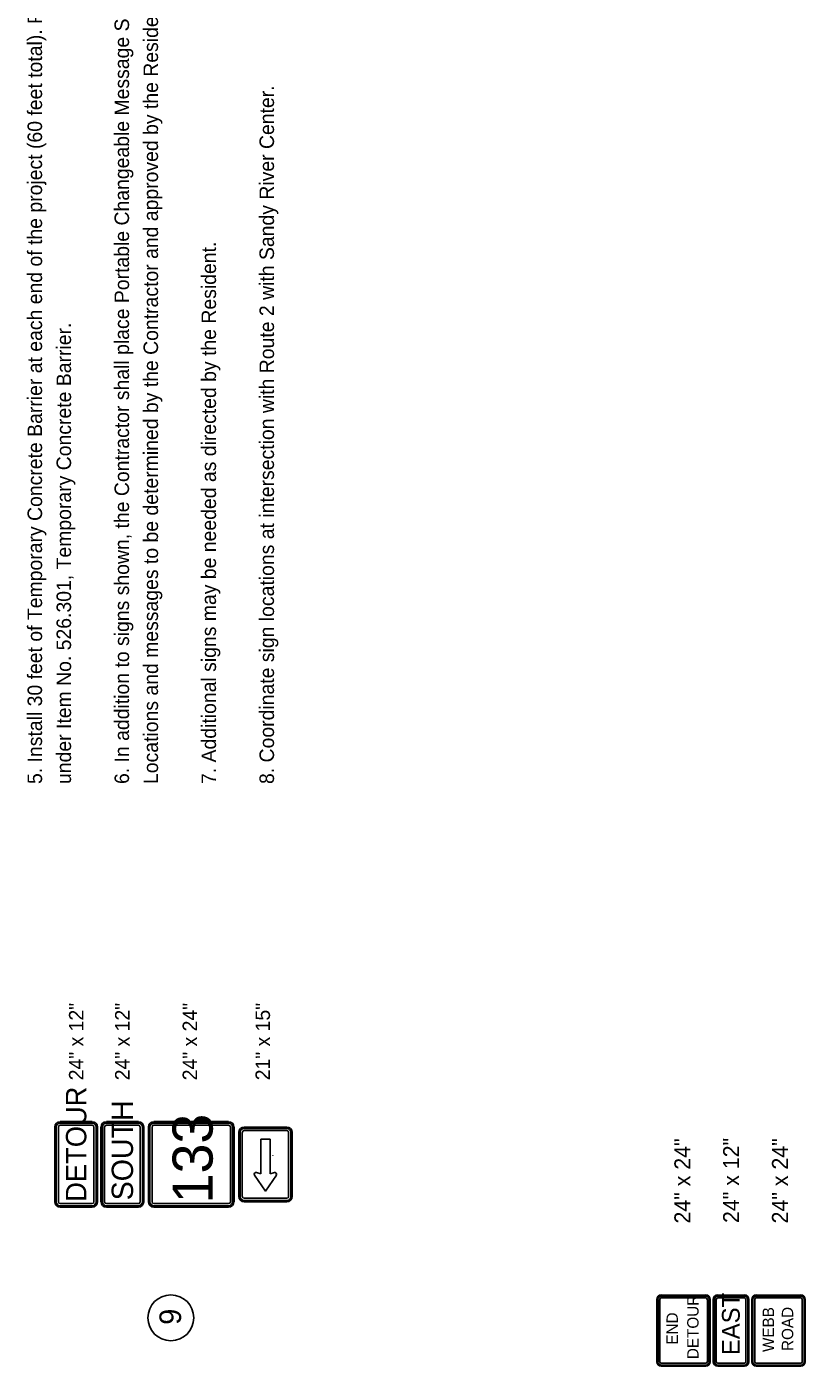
# Model space of a CAD drawing. Extents: x 1123038 to 1172987, y 554419 to 623636.
# Drawn here: x 1166973 to 1172987, y 559217 to 569560 of the extents above; entities that cross this region are included whole.
import ezdxf

# ---------------------------------------------------------------- set-up
doc = ezdxf.new("R2010")
doc.units = 0
for name, color, linetype in [('D_Text_Standard', 7, 'Continuous'), ('Default', 7, 'Continuous'), ('SIGNS TRAFFIC', 7, 'Continuous')]:
    doc.layers.add(name, color=color, linetype=linetype)

msp = doc.modelspace()

# ---------------------------------------------------------------- linework, layer by layer
at = {"layer": 'D_Text_Standard'}
msp.add_circle((1168086, 559591), 177, dxfattribs=at)
at = {"layer": 'Default'}
for p, q in [((1172219, 559767), (1171875, 559767)), ((1172517, 559767), (1172311, 559767)), ((1172952, 559767), (1172609, 559767)), ((1171841, 559733), (1171841, 559252)), ((1171850, 559733), (1171850, 559252)), ((1171864, 559252), (1171864, 559733)), ((1172219, 559759), (1171875, 559759)), ((1171875, 559744), (1172219, 559744)), ((1172231, 559733), (1172231, 559252)), ((1172245, 559252), (1172245, 559733)), ((1172253, 559252), (1172253, 559733)), ((1172276, 559733), (1172276, 559252)), ((1172285, 559733), (1172285, 559252)), ((1172299, 559252), (1172299, 559733)), ((1172517, 559759), (1172311, 559759)), ((1172311, 559744), (1172517, 559744)), ((1172528, 559733), (1172528, 559252)), ((1172543, 559252), (1172543, 559733)), ((1172551, 559252), (1172551, 559733)), ((1172574, 559733), (1172574, 559252)), ((1172583, 559733), (1172583, 559252)), ((1172597, 559252), (1172597, 559733)), ((1172952, 559759), (1172609, 559759)), ((1172609, 559744), (1172952, 559744)), ((1172964, 559733), (1172964, 559252)), ((1172978, 559252), (1172978, 559733)), ((1172987, 559252), (1172987, 559733)), ((1172219, 559240), (1171875, 559240)), ((1171875, 559226), (1172219, 559226)), ((1171875, 559217), (1172219, 559217)), ((1172517, 559240), (1172311, 559240)), ((1172311, 559226), (1172517, 559226)), ((1172311, 559217), (1172517, 559217)), ((1172952, 559240), (1172609, 559240)), ((1172609, 559226), (1172952, 559226)), ((1172609, 559217), (1172952, 559217))]:
    msp.add_line(p, q, dxfattribs=at)
for centre, radius, start, end in [((1171875, 559733), 34.4, 90, 180), ((1172219, 559733), 34.4, 0, 90), ((1172311, 559733), 34.4, 90, 180), ((1172517, 559733), 34.4, 0, 90), ((1172609, 559733), 34.4, 90, 180), ((1172952, 559733), 34.4, 0, 90), ((1171875, 559733), 25.8, 90, 180), ((1171875, 559733), 11.5, 90, 180), ((1172219, 559733), 25.8, 0, 90), ((1172219, 559733), 11.5, 0, 90), ((1172311, 559733), 25.8, 90, 180), ((1172311, 559733), 11.5, 90, 180), ((1172517, 559733), 25.8, 0, 90), ((1172517, 559733), 11.5, 0, 90), ((1172609, 559733), 25.8, 90, 180), ((1172609, 559733), 11.5, 90, 180), ((1172952, 559733), 25.8, 0, 90), ((1172952, 559733), 11.5, 0, 90), ((1171875, 559252), 34.4, 180, 270), ((1171875, 559252), 25.8, 180, 270), ((1171875, 559252), 11.5, 180, 270), ((1172219, 559252), 34.4, 270, 0), ((1172219, 559252), 25.8, 270, 0), ((1172219, 559252), 11.5, 270, 0), ((1172311, 559252), 34.4, 180, 270), ((1172311, 559252), 25.8, 180, 270), ((1172311, 559252), 11.5, 180, 270), ((1172517, 559252), 34.4, 270, 0), ((1172517, 559252), 25.8, 270, 0), ((1172517, 559252), 11.5, 270, 0), ((1172609, 559252), 34.4, 180, 270), ((1172609, 559252), 25.8, 180, 270), ((1172609, 559252), 11.5, 180, 270), ((1172952, 559252), 34.4, 270, 0), ((1172952, 559252), 25.8, 270, 0), ((1172952, 559252), 11.5, 270, 0)]:
    msp.add_arc(centre, radius, start, end, dxfattribs=at)
at = {"layer": 'SIGNS TRAFFIC'}
for p, q in [((1168621, 560528), (1168621, 561023)), ((1168781, 560702), (1168781, 560971)), ((1168781, 560971), (1168853, 560971)), ((1168853, 560971), (1168853, 560702)), ((1168747, 560713), (1168781, 560702)), ((1168853, 560702), (1168887, 560713))]:
    msp.add_line(p, q, dxfattribs=at)
for points in [[(1167231, 561106), (1167478, 561106)], [(1167231, 561106), (1167478, 561106)], [(1167588, 561106), (1167835, 561106)], [(1167588, 561106), (1167835, 561106)], [(1167955, 561106), (1168532, 561106)], [(1167955, 561106), (1168532, 561106)], [(1167190, 560487), (1167190, 561064)], [(1167190, 560487), (1167190, 561064)], [(1167200, 560487), (1167200, 561064)], [(1167217, 561064), (1167217, 560487)], [(1167231, 561095), (1167478, 561095)], [(1167478, 561078), (1167231, 561078)], [(1167492, 560487), (1167492, 561064)], [(1167509, 561064), (1167509, 560487)], [(1167520, 561064), (1167520, 560487)], [(1167520, 561064), (1167520, 560487)], [(1167546, 560487), (1167546, 561064)], [(1167546, 560487), (1167546, 561064)], [(1167557, 560487), (1167557, 561064)], [(1167574, 561064), (1167574, 560487)], [(1167588, 561095), (1167835, 561095)], [(1167835, 561078), (1167588, 561078)], [(1167849, 560487), (1167849, 561064)], [(1167866, 561064), (1167866, 560487)], [(1167876, 561064), (1167876, 560487)], [(1167876, 561064), (1167876, 560487)], [(1167914, 560487), (1167914, 561064)], [(1167914, 560487), (1167914, 561064)], [(1167924, 560487), (1167924, 561064)], [(1167941, 561064), (1167941, 560487)], [(1167955, 561095), (1168532, 561095)], [(1168532, 561078), (1167955, 561078)], [(1168546, 560487), (1168546, 561064)], [(1168563, 561064), (1168563, 560487)], [(1168574, 561064), (1168574, 560487)], [(1168574, 561064), (1168574, 560487)], [(1168610, 561023), (1168610, 560528)], [(1168638, 561023), (1168638, 560528)], [(1168982, 561064), (1168652, 561064)], [(1168652, 561054), (1168982, 561054)], [(1168982, 561037), (1168652, 561037)], [(1168995, 560528), (1168995, 561023)], [(1169013, 561023), (1169013, 560528)], [(1169023, 560528), (1169023, 561023)], [(1168875, 560846), (1168874, 560845)], [(1168901, 560693), (1168817, 560569), (1168732, 560693)], [(1168652, 560514), (1168982, 560514)], [(1168982, 560497), (1168652, 560497)], [(1168652, 560487), (1168982, 560487)], [(1167231, 560473), (1167478, 560473)], [(1167478, 560456), (1167231, 560456)], [(1167478, 560446), (1167231, 560446)], [(1167478, 560446), (1167231, 560446)], [(1167588, 560473), (1167835, 560473)], [(1167835, 560456), (1167588, 560456)], [(1167835, 560446), (1167588, 560446)], [(1167835, 560446), (1167588, 560446)], [(1167955, 560473), (1168532, 560473)], [(1168532, 560456), (1167955, 560456)], [(1168532, 560446), (1167955, 560446)], [(1168532, 560446), (1167955, 560446)]]:
    msp.add_lwpolyline(points, dxfattribs=at)
for centre, radius, start, end in [((1167231, 561064), 41.2, 90, 180), ((1167231, 561064), 41.2, 90, 180), ((1167478, 561064), 41.2, 360, 90), ((1167478, 561064), 41.2, 360, 90), ((1167588, 561064), 41.2, 90, 180), ((1167588, 561064), 41.2, 90, 180), ((1167835, 561064), 41.2, 360, 90), ((1167835, 561064), 41.2, 360, 90), ((1167955, 561064), 41.2, 90, 180), ((1167955, 561064), 41.2, 90, 180), ((1168532, 561064), 41.2, 360, 90), ((1168532, 561064), 41.2, 360, 90), ((1167231, 561064), 30.9, 90, 180), ((1167231, 561064), 13.7, 90, 180), ((1167478, 561064), 30.9, 360, 90), ((1167478, 561064), 13.7, 360, 90), ((1167588, 561064), 30.9, 90, 180), ((1167588, 561064), 13.7, 90, 180), ((1167835, 561064), 30.9, 360, 90), ((1167835, 561064), 13.7, 360, 90), ((1167955, 561064), 30.9, 90, 180), ((1167955, 561064), 13.7, 90, 180), ((1168532, 561064), 30.9, 360, 90), ((1168532, 561064), 13.7, 360, 90), ((1168652, 561023), 41.2, 90, 180), ((1168652, 561023), 30.9, 90, 180), ((1168652, 561023), 13.7, 90, 180), ((1168982, 561023), 41.2, 360, 90), ((1168982, 561023), 30.9, 360, 90), ((1168982, 561023), 13.7, 360, 90), ((1168743, 560700), 12.9, 72.1872, 214.3237), ((1168890, 560700), 12.9, 325.6763, 107.8128), ((1167231, 560487), 41.2, 180, 270), ((1167231, 560487), 41.2, 180, 270), ((1167231, 560487), 30.9, 180, 270), ((1167231, 560487), 13.7, 180, 270), ((1167478, 560487), 41.2, 270, 360), ((1167478, 560487), 41.2, 270, 360), ((1167478, 560487), 30.9, 270, 360), ((1167478, 560487), 13.7, 270, 360), ((1167588, 560487), 41.2, 180, 270), ((1167588, 560487), 41.2, 180, 270), ((1167588, 560487), 30.9, 180, 270), ((1167588, 560487), 13.7, 180, 270), ((1167835, 560487), 41.2, 270, 360), ((1167835, 560487), 41.2, 270, 360), ((1167835, 560487), 30.9, 270, 360), ((1167835, 560487), 13.7, 270, 360), ((1167955, 560487), 41.2, 180, 270), ((1167955, 560487), 41.2, 180, 270), ((1167955, 560487), 30.9, 180, 270), ((1167955, 560487), 13.7, 180, 270), ((1168532, 560487), 41.2, 270, 360), ((1168532, 560487), 41.2, 270, 360), ((1168532, 560487), 30.9, 270, 360), ((1168532, 560487), 13.7, 270, 360), ((1168652, 560528), 41.2, 180, 270), ((1168652, 560528), 30.9, 180, 270), ((1168652, 560528), 13.7, 180, 270), ((1168982, 560528), 41.2, 270, 0), ((1168982, 560528), 30.9, 270, 0), ((1168982, 560528), 13.7, 270, 0)]:
    msp.add_arc(centre, radius, start, end, dxfattribs=at)

# ---------------------------------------------------------------- texts
at = {"layer": 'D_Text_Standard'}
for s, height, p in [('24" x 12"', 112, (1167411, 561425)), ('24" x 12"', 112, (1167767, 561425)), ('24" x 24"', 112, (1168289, 561425)), ('21" x 15"', 112, (1168852, 561425)), ('24" x 24"', 123.2, (1172099, 560319)), ('24" x 12"', 123.2, (1172476, 560323)), ('24" x 24"', 123.2, (1172853, 560320)), ('9', 167, (1168165, 559537))]:
    msp.add_text(s, height=height, rotation=90, dxfattribs=at).set_placement(p)
at = {"layer": 'Default'}
for s, height, p in [('5. Install 30 feet of Temporary Concrete Barrier at each end of the project (60 feet total). Payment will be made ', 112, (1167091, 563713)), ('6. In addition to signs shown, the Contractor shall place Portable Changeable Message Signs prior to closure.   ', 112, (1167763, 563713)), ('Locations and messages to be determined by the Contractor and approved by the Resident.', 112, (1167987, 563713)), ('8. Coordinate sign locations at intersection with Route 2 with Sandy River Center.', 112, (1168883, 563713)), ('7. Additional signs may be needed as directed by the Resident.', 112, (1168435, 563713)), ('under Item No. 526.301, Temporary Concrete Barrier.', 112, (1167315, 563713)), ('DETOUR', 88, (1172163, 559272)), ('EAST', 137.5, (1172481, 559303)), ('WEBB', 88, (1172746, 559327)), ('ROAD', 88, (1172894, 559335)), ('END', 88, (1172003, 559384))]:
    msp.add_text(s, height=height, rotation=90, dxfattribs=at).set_placement(p)
at = {"layer": 'SIGNS TRAFFIC'}
for s, height, p in [('DETOUR', 157.5, (1167433, 560487)), ('SOUTH', 165, (1167794, 560498)), ('133', 310, (1168409, 560475))]:
    msp.add_text(s, height=height, rotation=90, dxfattribs=at).set_placement(p)

doc.saveas('drawing.dxf')
